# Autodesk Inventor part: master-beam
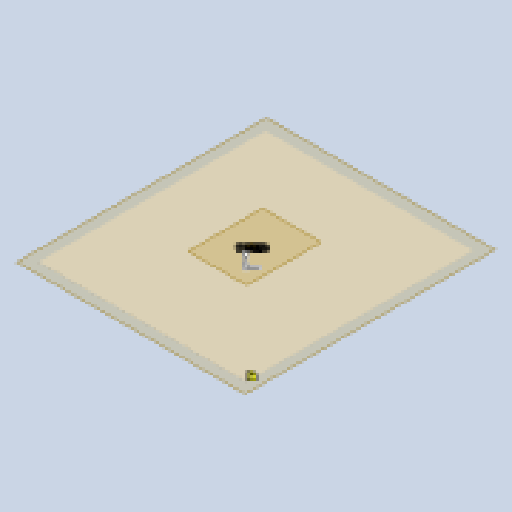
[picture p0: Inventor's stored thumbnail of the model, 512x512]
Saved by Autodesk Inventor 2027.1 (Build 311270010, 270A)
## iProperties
Created: 2026-07
Part Number: master-beam
Material: Generic
Document SubType Name: Modeling
Designer: dunge
Density: 1 g/cm^3
Appearance: Default
Author: dunge
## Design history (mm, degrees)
sketch "master sketch"
  geometry: L1 (0, 0)-(0, 228.6); L2 (0, 228.6)-(-114.3, 228.6); L3 (-114.3, 228.6)-(-114.3, 69.85); L4 (-292.1, 69.85)-(-292.1, 171.45); L5 (-342.9, 69.85)-(-342.9, -35.56); L6 (-342.9, -35.56)-(-241.3, -35.56); L7 (-342.9, -35.56)-(-342.9, 120.808); L8 (-114.3, 69.85)-(-114.3, -6.35); L9 (-342.9, -35.56)-(-342.9, -187.96); 31 further points; 1 other entity
  constraints: 24 point on line, 18 end point, 5 vertical, 3 perpendicular, 1 coincident, 1 midpoint, 10 other
  dimensions: "d0" = 228.6 distance of L1.start L1.end; "d1" = 304.8 distance of L3.end point (-419.1, 69.85); "d2" = 101.6 distance of L4.start L4.end; "d4" = 114.3 distance of L1.end L2.end; "d5" = 76.2 distance of L3.end L8.end; "d6" = 177.8 distance between parallel lines of L3 L4; "d9" = 19.05 distance of point (-190.5, 69.85) point (-171.45, 69.85); "d10" = 19.05 distance of point (-254, 69.85) point (-234.95, 69.85); "d11" = 44.45 distance of point (-234.95, 69.85) point (-190.5, 69.85); "d12" = 57.15 distance from line of L8 point (-171.45, 69.85); "d13" = 127 distance of L1.start point (0, 127); "d14" = 38.1 distance of point (-114.3, 190.5) point (-114.3, 152.4); "d15" = 38.1 distance from line of L2 point (-114.3, 190.5); "d16" = 17.78 distance of point (-342.9, 20.32) point (-342.9, 2.54); "d17" = 17.78 distance of point (-342.9, 20.32) point (-342.9, 38.1); "d18" = 16.51 distance of point (-342.9, -152.4) point (-342.9, -168.91); "d20" = 16.51 distance of point (-342.9, -73.66) point (-342.9, -90.17); "d26" = 152.4 distance of L5.end L9.end; "d27" = 31.75 distance of L5.start point (-342.9, 38.1); "d29" = 35.56 distance of point (-269.24, -35.56) point (-304.8, -35.56); "d40" = 38.1 distance from line of point (-342.9, -73.66) L6; "d42" = 21.59 distance of point (-342.9, -111.76) point (-342.9, -90.17); "d43" = 15.24 distance of point (-342.9, -137.16) point (-342.9, -152.4); "d44" = 25.4 distance of point (-342.9, -137.16) point (-342.9, -111.76); "d45" = 25.4 distance of point (0, 171.45) point (0, 146.05); "d46" = 19.05 distance of point (0, 146.05) point (0, 127); "d47" = 31.75 distance of L3.end point (-114.3, 38.1); "d48" = 31.75 distance of L3.end point (-114.3, 101.6); "d49" = 50.8 distance of point (-114.3, 101.6) point (-114.3, 152.4); "d51" = 31.75 distance of L3.end point (-146.05, 69.85); "d52" = 20.32 distance of point (-292.1, 101.6) point (-292.1, 121.92); "d53" = 20.32 distance of point (-292.1, 142.24) point (-292.1, 121.92); "d54" = 31.75 distance of L4.start point (-292.1, 101.6); "d87" = 101.6 distance of L5.end L6.end; "d88" = 17.78 distance of point (-304.8, -35.56) point (-287.02, -35.56); "d89" = 38.1 distance from line of L7 point (-304.8, -35.56); "d90" = 38.1 distance of point (-342.9, 2.54) L5.end; "d94" = 50.8 distance between parallel lines of L4 L7
workpoint "Work Point1"
workpoint "Work Point2"
workpoint "Work Point3"
workpoint "Work Point4"
workpoint "Work Point5"
workpoint "Work Point6"
workpoint "Work Point7"
workpoint "Work Point8"
workpoint "Work Point9"
workpoint "Work Point10"
workpoint "Work Point11"
workpoint "Work Point12"
workpoint "Work Point13"
workpoint "Work Point14"
workpoint "Work Point15"
workpoint "Work Point16"
workpoint "Work Point17"
workpoint "Work Point18"
workpoint "Work Point19"
workpoint "Work Point20"
workpoint "Work Point21"
workpoint "Work Point22"
workpoint "Work Point23"
workpoint "Work Point24"
workpoint "Work Point25"
sketch "Sketch2"
  geometry: L1 (-114.3, 69.85)-(-419.1, 69.85) reference; L2 (-114.3, 59.69)-(-419.1, 59.69); L3 (-419.1, 59.69)-(-419.1, 69.85); L4 (-114.3, 59.69)-(-114.3, 69.85); 1 further point
  constraints: 6 end point, 2 parallel, 1 vertical
  dimensions: "THICK_BEAM_RADIUS" = 10.16 distance between parallel lines of L1 L2
revolve "Revolution1" sketch "Sketch2" stored, may be unused: angle "d23" = 90 deg
workpoint "Work Point26"
sketch "Sketch3"
  geometry: L1 (-292.1, 69.85)-(-292.1, 171.45) reference; L2 (-302.26, 59.831)-(-302.26, 143.51); L3 (-302.26, 59.831)-(-292.1, 59.831); L4 (-302.26, 143.51)-(-297.307, 171.858); L5 (-297.307, 171.858)-(-297.307, 176.674); L6 (-297.307, 176.674)-(-292.1, 176.674); L7 (-292.1, 176.674)-(-292.1, 171.45); L8 (-292.1, 59.831)-(-292.1, 69.85); 2 further points
  constraints: 14 end point, 2 perpendicular, 2 vertical, 1 collinear, 1 parallel
  dimensions: "d24" = 10.16 distance between parallel lines of L1 L2 (derived); "d56" = 1.27 vertical distance of L2.end point (-292.1, 142.24); "d57" = 5.207 distance between parallel lines of L7 L5; "d58" = 5.22357 distance of L6.end L1.end; "d59" = 4.81531 distance of L4.end L5.end
revolve "LED Beam" sketch "Sketch3" stored, may be unused: angle "d25" = 360 deg
workpoint "Work Point27"
workpoint "Work Point28"
workpoint "Work Point29"
workpoint "Work Point30"
workpoint "Work Point31"
workpoint "Work Point32"
workpoint "Work Point33"
workpoint "Work Point34"
workpoint "Work Point35"
workpoint "Work Point36"
sketch "Sketch4"
  geometry: L1 (-114.3, 228.6)-(-114.3, 69.85) reference; L2 (-104.14, -6.35)-(-104.14, 152.4); L3 (-111.76, 152.4)-(-116.84, 152.4); L4 (-114.3, -6.35)-(-104.14, -6.35); L5 (-111.76, 228.6)-(-114.3, 228.6); L6 (-116.84, 190.5)-(-111.76, 190.5); L7 (-111.76, 190.5)-(-111.76, 228.6); L8 (-104.14, 152.4)-(-114.046, 183.356); L9 (-114.046, 183.356)-(-111.76, 190.5); L10 (-114.3, 69.85)-(-114.3, -6.35) reference; L11 (-113.965, 183.61)-(-114.3, 183.61); L12 (-113.965, 183.102)-(-114.3, 183.102); 4 further points
  constraints: 21 end point, 4 perpendicular, 4 point on line, 2 midpoint, 2 parallel, 2 vertical, 1 horizontal, 1 horizontal alignment, 1 vertical alignment
  dimensions: "d33" = 0.254 distance from line of L1 L8.end; "d60" = 0.254 distance from line of L8.end L11; "d61" = 0.254 distance from line of L8.end L12; "THIN_BEAM_RADIUS" = 2.54 distance between parallel lines of L1 L7; "d63" = 10.16 distance between parallel lines of L1 L2 (derived)
revolve "Revolution3" sketch "Sketch4" stored, may be unused: angle "d34" = 360 deg
workplane "Work Plane1"
sketch "Sketch6"
  geometry: L1 (11597.715, 14740.167)-(-14176.276, 14740.167); L2 (-14176.276, 14740.167)-(-14176.276, -13449.358); L3 (-14176.276, -13449.358)-(11597.715, -13449.358); L4 (11597.715, -13449.358)-(11597.715, 14740.167); 1 further point
  constraints: 8 end point, 2 parallel, 1 horizontal, 1 perpendicular
extrude "Extrusion2" new body sketch "Sketch6" distance "d38" = 25.4; taper "d39" = 0 deg
workpoint "Work Point37"
workpoint "Work Point38"
workpoint "Work Point39"
workpoint "Work Point40"
workpoint "Work Point41"
workpoint "Work Point42"
workpoint "Work Point43"
workpoint "Work Point44"
workplane "Work Plane2"
sketch "Sketch7"
  geometry: L1 (0, 228.6)-(-114.3, 228.6) reference; L2 (0, 0)-(0, 228.6) reference; L3 (0, 145.605)-(0, 146.494) reference; 3 further points
  constraints: 2 end point, 1 vertical, 2 other
workpoint "Work Point45"
workpoint "Work Point46"
workpoint "Work Point47"
workpoint "Work Point48"
workpoint "Work Point49"
sketch "Sketch8"
  geometry: L1 (-116.84, 228.6)-(-111.76, 228.6) reference; 2 further points
  constraints: 1 horizontal alignment, 1 midpoint, 2 other
extrude "Extrusion3" join sketch "Sketch8" distance "d64" = 19.05; taper "d65" = 0 deg
workplane "Work Plane3"
sketch "Sketch9"
  geometry: L1 (2.54, 0)-(-2.54, 0) reference; C1 r 12.7 at (0, 0); 1 further point
  constraints: 1 centre point, 1 midpoint
  dimensions: "d66" = 25.4 diameter of C1
extrude "Extrusion4" cut sketch "Sketch9" distance "d67" = 19.05; taper "d68" = 0 deg
sketch "Sketch10"
  geometry: L1 (0, 228.6)-(-114.3, 228.6) reference; L2 (0, 0)-(0, 228.6) reference; L3 (-114.3, 228.6)-(0, 228.6); L4 (0, 228.6)-(0, 231.14); L5 (0, 231.14)-(-114.3, 231.14); L6 (-114.3, 231.14)-(-114.3, 228.6); L7 (0, 228.6)-(2.54, 228.6); L8 (2.54, 228.6)-(2.54, 0); L9 (2.54, 0)-(0, 0); L10 (0, 0)-(0, 228.6); 4 further points
  constraints: 16 end point, 4 parallel, 2 horizontal, 2 perpendicular
  dimensions: "d69" = 2.54 distance of L8.end L9.end (derived); "d70" = 2.54 distance of L3.end L4.end (derived)
revolve "Revolution4" stored, may be unused: angle "d71" = 90 deg
revolve "Revolution5" stored, may be unused: angle "d72" = 360 deg
workplane "Work Plane4"
sketch "Sketch11"
  geometry: C1 r 10.368 at (-0.227, -0.06); 1 further point
  constraints: 1 centre point
extrude "Extrusion5" cut sketch "Sketch11" distance "d73" = 19.05; taper "d74" = 0 deg
workplane "Work Plane5"
sketch "Sketch12"
  geometry: L1 (-2.54, 0)-(2.54, 0) reference; C1 r 24.504 at (-0.617, 0); 1 further point
  constraints: 1 centre point, 1 point on line
extrude "Extrusion6" cut sketch "Sketch12" distance "d75" = 19.05; taper "d76" = 0 deg
sketch "Sketch13"
  geometry: L1 (-342.9, 54.915)-(-342.9, 84.785) reference; L2 (-357.835, 69.85)-(-327.965, 69.85) reference; L3 (-342.9, 20.411)-(-342.9, -33.65) reference; L4 (-241.554, -25.281)-(-241.554, -46.853) reference; L5 (-352.74, -183.96)-(-333.06, -183.96) reference; L6 (-342.9, -280.735)-(-342.9, -133.286) reference; L7 (-342.9, 69.85)-(-332.74, 59.69); L8 (-332.74, 59.69)-(-332.74, -10.16); L9 (-332.74, -10.16)-(-342.9, -35.56); L10 (-342.9, -35.56)-(-317.5, -45.72); L11 (-342.9, -35.56)-(-353.06, -60.96); L12 (-342.9, 54.915)-(-342.9, 2.54); L13 (-353.06, -60.96)-(-353.06, -168.91); L14 (-353.06, -168.91)-(-346.71, -183.96); L15 (-342.9, -133.286)-(-342.9, -33.65); L16 (-317.5, -45.72)-(-269.24, -45.72); L17 (-269.24, -45.72)-(-239.875, -38.733); L18 (-239.875, -38.733)-(-239.875, -35.56); L19 (-241.241, -35.56)-(-342.9, -35.56); L20 (-241.241, -35.56)-(-239.875, -35.56); L21 (-241.554, -35.56)-(-241.554, -39.132); L22 (-342.9, -35.56)-(-353.06, -60.96); L23 (-353.06, -168.91)-(-346.71, -183.96); L24 (-342.9, -183.96)-(-342.9, -35.56); 9 further points
  constraints: 44 end point, 8 vertical, 6 point on line, 3 collinear, 3 horizontal, 3 perpendicular, 2 midpoint, 1 horizontal alignment, 1 vertical alignment, 8 other
  dimensions: "d78" = 45 deg angle of L1 L7; "d79" = 10.16 distance between parallel lines of L1 L8 (derived); "d80" = 10.16 distance between parallel lines of L15 L13 (derived); "d82" = 3.17252 distance of L17.end L18.end; "d83" = 1.67902 distance from line of L17.end L4; "d84" = 3.81 distance from line of L6 L14.end; "d91" = 10.16 distance between parallel lines of L19 L16 (derived)
revolve "Revolution6" sketch "Sketch13" stored, may be unused: angle "d92" = 360 deg
sketch "Sketch14"
  geometry: L1 (-239.875, -38.733)-(-239.875, -35.56) reference; L2 (-241.241, -35.56)-(-342.9, -35.56) reference; L3 (-241.241, -35.56)-(-239.875, -35.56) reference; L4 (-269.24, -45.72)-(-239.875, -38.733) reference; L5 (-342.9, -35.56)-(-317.5, -45.72) reference; L6 (-317.5, -45.72)-(-269.24, -45.72) reference; 1 further point
revolve "Revolution7" sketch "Sketch14" stored, may be unused: angle "d93" = 360 deg
sketch "Sketch15"
  geometry: L1 (-281.94, 69.85)-(-419.1, 69.85); L2 (-419.1, 69.85)-(-419.1, 80.01); L3 (-419.1, 80.01)-(-281.94, 80.01); L4 (-281.94, 80.01)-(-281.94, 69.85); 2 further points
  constraints: 8 end point, 2 parallel, 1 coincident, 1 horizontal, 1 perpendicular
  dimensions: "d95" = 10.16 distance of L1.end L2.end (derived)
revolve "Revolution8" sketch "Sketch15" stored, may be unused: angle "d96" = 90 deg
workplane "Work Plane6"
sketch "Sketch16"
  geometry: C1 r 22.998 at (0, -0.97); 1 further point
  constraints: 1 centre point
extrude "Extrusion7" cut sketch "Sketch16" distance "d97" = 25.4; taper "d98" = 0 deg
sketch "Sketch17"
  geometry: L1 (-342.9, -133.286)-(-342.9, -33.65) reference; L2 (-342.9, -35.56)-(-353.06, -60.96) reference; L3 (-353.06, -60.96)-(-353.06, -168.91) reference; L4 (-353.06, -168.91)-(-346.71, -183.96) reference; L5 (-342.9, -183.96)-(-342.9, -35.56) reference; L6 (-346.71, -183.96)-(-342.9, -183.96); 1 further point
  constraints: 2 end point, 1 horizontal
revolve "Revolution9" sketch "Sketch17" stored, may be unused: angle "d99" = 90 deg
node "red beam"
node "blue beam"
node "red beam 2"
node "white plane"
node "Reference1"
node "Reference2"
node "green beam"
node "blue beam 2"
node "green 2"
body "Solid9"
other parameters: "d37" = -38.1, "d55" = -19.05
